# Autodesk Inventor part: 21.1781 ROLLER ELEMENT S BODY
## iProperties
Created: 2007-05
Part Number: 21.1781 ROLLER ELEMENT S BODY
Material: PVC-U
Document SubType Name: Modeling
Designer: Andy Moles
Mass: 15.0925 g
Surface Area: 46.9354 cm^2
Volume: 10.7804 cm^3
Density: 1.4 g/cm^3
Author: Andy Moles
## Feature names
1. Revolution1
